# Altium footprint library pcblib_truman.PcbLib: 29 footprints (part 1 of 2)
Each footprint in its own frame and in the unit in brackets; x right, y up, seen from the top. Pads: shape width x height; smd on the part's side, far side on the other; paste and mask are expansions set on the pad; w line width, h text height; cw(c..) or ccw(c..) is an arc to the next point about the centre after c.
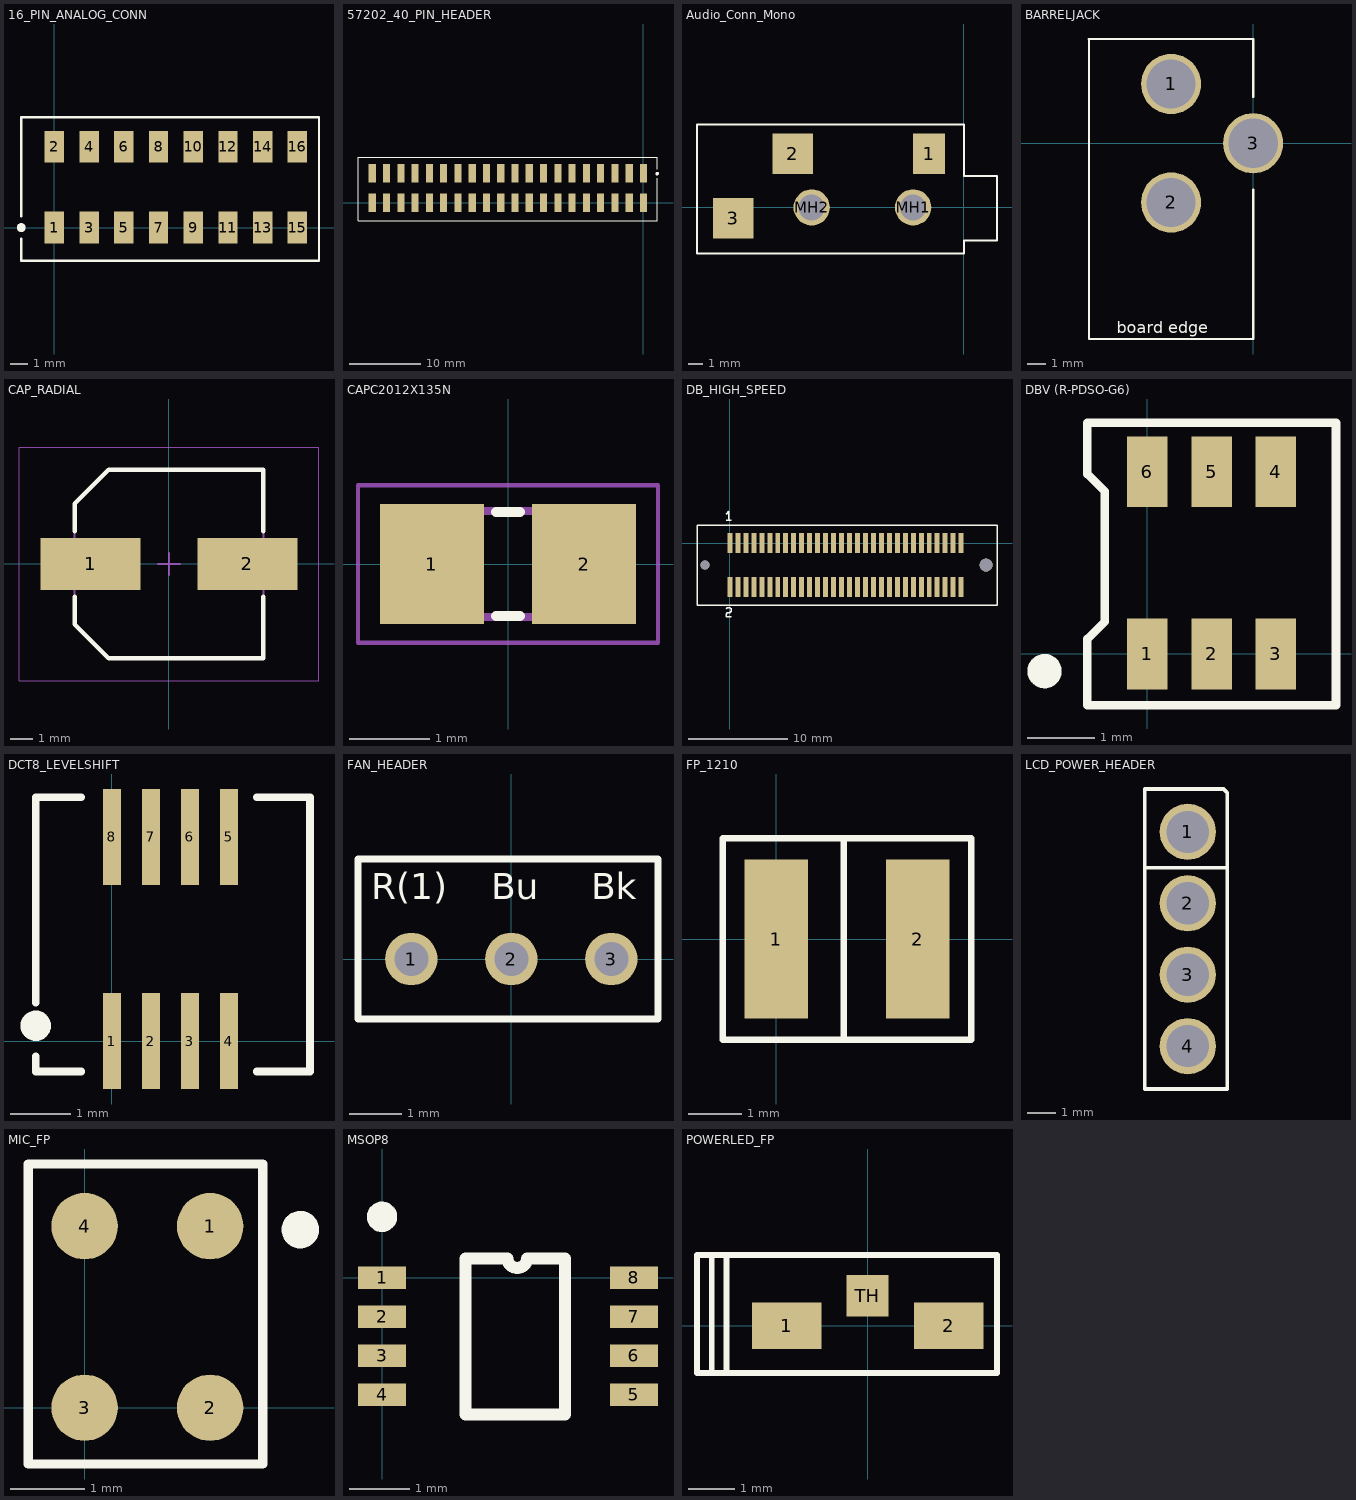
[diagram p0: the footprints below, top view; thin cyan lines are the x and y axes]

## 16_PIN_ANALOG_CONN [mm]
pads (16):
  rect 1.12x1.83 smd: 1(0,0) 2(0,4.65) 3(2,0) 4(2,4.65) 5(4,0) 6(4,4.65) 7(6,0) 8(6,4.65) 9(8,0) 10(8,4.65) 11(10,0) 12(10,4.65) 13(12,0) 14(12,4.65) 15(14,0) 16(14,4.65)
Top Overlay:
  circle w0.254: c-1.905,0 r0.127
  lines w0.127: -1.905,-0.635 -1.905,-1.905 15.24,-1.905 15.24,6.35 -1.905,6.35 -1.905,0.635

## 57202_40_PIN_HEADER [mm]
pads (40):
  rect 1x2.6 smd: 1(0,4.1) 2(0,0) 3(-2,4.1) 4(-2,0) 5(-4,4.1) 6(-4,0) 7(-6,4.1) 8(-6,0) 9(-8,4.1) 10(-8,0) 11(-10,4.1) 12(-10,0) 13(-12,4.1) 14(-12,0) 15(-14,4.1) 16(-14,0) 17(-16,4.1) 18(-16,0) 19(-18,4.1) 20(-18,0) 21(-20,4.1) 22(-20,0) 23(-22,4.1) 24(-22,0) 25(-24,4.1) 26(-24,0) 27(-26,4.1) 28(-26,0) 29(-28,4.1) 30(-28,0) 31(-30,4.1) 32(-30,0) 33(-32,4.1) 34(-32,0) 35(-34,4.1) 36(-34,0) 37(-36,4.1) 38(-36,0) 39(-38,4.1) 40(-38,0)
Top Overlay:
  circle w0.254: c1.905,4.064 r0.127
  lines w0.127: 1.905,3.429 1.905,-2.54 -40.005,-2.54 -40.005,6.35 1.905,6.35 1.905,4.699

## Audio_Conn_Mono [mm]
pads (5):
  rect 2.2x2.8 smd: 1(-2.4,3.7)
  rect 2.8x2.8 smd: 2(-11.8,3.7) 3(-15.9,-0.75)
  round 2.5 hole 1.8 unplated: MH1(-3.5,0) MH2(-10.5,0)
Top Overlay:
  lines w0.127: -18.415,-3.175 -18.415,5.715 -12.065,5.715 0,5.715 0,2.159 2.286,2.159 2.286,-1.905 2.286,-2.286 0,-2.286 0,-3.175 -18.415,-3.175

## BARRELJACK [mm]
pads (3):
  round 3.3 hole 2.7: 1(-4.5,3.25) 2(-4.5,-3.25) 3(0,0)
Top Overlay:
  lines w0.127: 0,-2.54 0,-10.74 -9,-10.74 -9,5.698 -9.017,5.715 0,5.715 0,2.54
  text "board edge" at -7.493,-10.414 h0.64

## CAP_RADIAL [mm] "Aluminum Electrolytic Capacitor, Body 8.30x8.30x10.50mm, IPC Low Density"
height 10.5
pads (2):
  rect 4.5x2.35 smd: 1(-3.525,0) 2(3.525,0)
Top Overlay:
  lines w0.2: -4.25,-1.475 -4.25,-2.713 -2.712,-4.25 4.25,-4.25 4.25,-1.475 ; -4.25,1.475 -4.25,2.712 -2.712,4.25 4.25,4.25 4.25,1.475
Mechanical 13:
  lines w0.1: -4.25,-2.713 -2.712,-4.25 4.25,-4.25 4.25,4.25 -2.712,4.25 -4.25,2.712 -4.25,-2.713
Mechanical 15:
  lines w0.05: -6.75,-5.25 -6.75,5.25 6.75,5.25 6.75,-5.25 -6.75,-5.25
  lines w0.1: -0.5,0 0.5,0 ; 0,-0.5 0,0.5
3D body: height 3.5, standoff 0, extent -4.25,-4.25 4.25,4.25
3D body: height 10.5, standoff 0, extent -4.25,-4.25 4.216,4.233

## CAPC2012X135N [mm]
pads (2):
  rect 1.3x1.5 smd: 1(-0.95,0) 2(0.95,0)
Top Overlay:
  lines w0.127: -0.15,-0.65 0.15,-0.65 ; -0.15,0.65 0.15,0.65
Mechanical 1:
  region: -1.093,0.726 -0.342,0.726 -0.342,-0.724 -1.093,-0.724
  region: 0.356,0.726 1.106,0.726 1.106,-0.724 0.356,-0.724
  lines w0.051: -1.873,-0.983 1.873,-0.983 1.873,0.983 -1.873,0.983 -1.873,-0.983
  lines w0.102: -0.381,0.66 0.381,0.66 ; -0.356,-0.66 0.381,-0.66

## DB_HIGH_SPEED [mm]
pads (62):
  rect 0.5x2 smd: 1(0,0) 2(0,-4.4) 3(0.8,0) 4(0.8,-4.4) 5(1.6,0) 6(1.6,-4.4) 7(2.4,0) 8(2.4,-4.4) 9(3.2,0) 10(3.2,-4.4) 11(4,0) 12(4,-4.4) 13(4.8,0) 14(4.8,-4.4) 15(5.6,0) 16(5.6,-4.4) 17(6.4,0) 18(6.4,-4.4) 19(7.2,0) 20(7.2,-4.4) 21(8,0) 22(8,-4.4) 23(8.8,0) 24(8.8,-4.4) 25(9.6,0) 26(9.6,-4.4) 27(10.4,0) 28(10.4,-4.4) 29(11.2,0) 30(11.2,-4.4) 31(12,0) 32(12,-4.4) 33(12.8,0) 34(12.8,-4.4) 35(13.6,0) 36(13.6,-4.4) 37(14.4,0) 38(14.4,-4.4) 39(15.2,0) 40(15.2,-4.4) 41(16,0) 42(16,-4.4) 43(16.8,0) 44(16.8,-4.4) 45(17.6,0) 46(17.6,-4.4) 47(18.4,0) 48(18.4,-4.4) 49(19.2,0) 50(19.2,-4.4) 51(20,0) 52(20,-4.4) 53(20.8,0) 54(20.8,-4.4) 55(21.6,0) 56(21.6,-4.4) 57(22.4,0) 58(22.4,-4.4) 59(23.2,0) 60(23.2,-4.4)
  round 0.9 hole 0.9 unplated: MH1(-2.5,-2.2)
  round 1.3 hole 1.3 unplated: MH2(25.7,-2.2)
Top Overlay:
  lines w0.127: -0.381,-6.604 -0.254,-6.477 0,-6.477 0.127,-6.604 0.127,-6.858 0,-6.985 -0.254,-6.985 -0.381,-7.112 -0.381,-7.366 0.127,-7.366 ; -0.381,2.286 -0.127,2.286 ; -0.381,2.921 -0.127,3.175 -0.127,2.286 ; 0.127,2.286 -0.127,2.286 ; -3.302,-6.223 -3.302,1.778 26.797,1.778 26.797,-6.223 -3.302,-6.223

## DBV (R-PDSO-G6) [mm] "6 pin dbv"
pads (6):
  rect 0.6x1.05 smd: 1(0,0) 2(0.95,0) 3(1.9,0) 4(1.9,2.7) 5(0.95,2.7) 6(0,2.7)
Top Overlay:
  circle w0.254: c-1.524,-0.254 r0.127
  lines w0.127: -0.889,-0.762 -0.889,0.222 -0.635,0.476 -0.635,2.413 -0.889,2.667 -0.889,3.175 -0.889,3.429 2.794,3.429 2.794,-0.762 -0.889,-0.762

## DCT8_LEVELSHIFT [mm]
pads (8):
  rect 0.3x1.6 smd: 1(0,0) 2(0.65,0) 3(1.3,0) 4(1.95,0) 5(1.95,3.4) 6(1.3,3.4) 7(0.65,3.4) 8(0,3.4)
Top Overlay:
  circle w0.254: c-1.27,0.254 r0.127
  lines w0.127: -1.27,-0.254 -1.27,-0.508 -0.508,-0.508 ; -1.27,0.635 -1.27,4.064 -0.508,4.064 ; 2.413,-0.508 3.302,-0.508 3.302,4.064 2.413,4.064

## DragonBoard_Connector [mm]

## FAN_HEADER [mm]
pads (3):
  round 1 hole 0.65: 1(-1.905,0) 2(0,0) 3(1.905,0)
Top Overlay:
  lines w0.127: -2.921,-1.143 -2.921,1.905 2.794,1.905 2.794,-1.143 -2.921,-1.143
  text "Bk" at 1.524,1.143 h0.5
  text "Bu" at -0.381,1.143 h0.5
  text "R(1)" at -2.667,1.143 h0.5

## FP_1210 [mm]
pads (2):
  rect 1.2x3 smd: 1(0,0) 2(2.667,0)
Top Overlay:
  lines w0.127: 1.27,-1.905 1.27,1.905 ; 1.27,1.905 3.683,1.905 3.683,-1.905 -1.016,-1.905 -1.016,1.905 1.27,1.905

## LCD_POWER_HEADER [mm]
pads (4):
  round 2 hole 1.5: 1(7.874,33.274) 2(7.874,30.734) 3(7.874,28.194) 4(7.874,25.654)
Top Overlay:
  lines w0.127: 6.35,34.544 6.35,34.798 9.144,34.798 9.271,34.671 9.271,34.417 9.271,33.56 9.271,32.861 9.271,32.004 ; 6.35,34.544 6.35,24.13 9.271,24.13 9.271,32.004 ; 6.35,34.544 6.35,32.004 9.271,32.004

## MIC_FP [mm]
pads (4):
  round 0.9 smd: 1(1.7,2.46) 2(1.7,0) 3(0,0) 4(0,2.46)
Top Overlay:
  circle w0.254: c2.921,2.413 r0.127
  lines w0.127: -0.762,-0.762 2.413,-0.762 2.413,3.302 0.889,3.302 -0.762,3.302 -0.762,-0.762

## MSOP8 [mm]
pads (8):
  rect 0.8x0.38 smd: 1(0,0) 2(0,-0.65) 3(0,-1.3) 4(0,-1.95) 5(4.2,-1.95) 6(4.2,-1.3) 7(4.2,-0.65) 8(4.2,0)
Top Overlay:
  circle w0.254: c0,1.016 r0.127
  lines w0.2: 1.389,-2.275 3.048,-2.275 3.048,0.325 2.416,0.325 cw(c2.254,0.325) 2.091,0.325 1.389,0.325 1.389,-2.275

## POWERLED_FP [mm]
pads (3):
  rect 1.5x1 smd: 1(-1.75,0) 2(1.75,0)
  rect 0.9x0.9 smd: TH(0,0.65)
Top Overlay:
  lines w0.127: -3.365,-1.016 -3.365,1.524 ; -3.048,-1.016 -3.048,1.524 ; -3.048,1.524 2.794,1.524 2.794,1.016 2.794,-1.016 -2.794,-1.016 -3.683,-1.016 -3.683,1.524 -3.048,1.524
